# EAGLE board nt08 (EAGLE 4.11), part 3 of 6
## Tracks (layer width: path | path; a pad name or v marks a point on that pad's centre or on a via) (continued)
GND  (via drill 0.61) (continued)
  Bottom 0.254: IC7.12 -2.54,546.1 -6.35,542.29 -6.35,537.85 0.64,537.85 1.27,538.48 1.27,541.65 5.71,541.65 6.99,540.38 IC7.7 | M916_4.C2 44.45,574.04 44.45,578.49 8.26,578.49 IC8.7 | M916_2.T1 85.72,424.81 84.45,426.08 52.07,426.08 47.62,421.64 45.72,421.64 M916_2.C2 | IC47.7 247.01,90.81 245.75,89.53 v243.84,89.53 239.4,89.53 238.12,90.81 IC47.3 236.85,90.81 235.59,89.53 202.56,89.53 | 202.56,89.53 169.54,89.53 168.28,90.81 IC23.7 | 202.56,89.53 203.84,90.81 IC36.4 | v275.59,14.61 248.28,14.61 IC46.7 | IC46.6 244.47,14.61 243.21,13.34 239.4,13.34 238.12,14.61 IC46.3 236.85,15.88 235.59,17.14 206.38,17.14 205.1,15.88 IC34.4 203.84,14.61 202.56,13.34 169.54,13.34 168.28,14.61 IC22.7 167,15.88 165.74,17.14 89.53,17.14 88.27,15.88 IC16.7 87,14.61 85.72,13.34 46.35,13.34 | M916_21.C2 -35.56,313.06 -34.29,311.79 -24.13,311.79 -20.95,308.61 5.71,308.61 6.35,309.25 6.35,316.23 5.71,316.23 M916_21.T1 | 3.17,467.36 4.45,468.63 M916_23.T1 | 3.17,467.36 -34.29,467.36 -35.56,466.09 M916_23.C2 | 4.45,414.65 3.17,415.93 IC4.5 | 4.45,414.65 5.71,414.65 6.99,415.93 IC4.7 | 4.45,414.65 -15.88,394.33 -35.56,394.33 -35.56,389.89 M916_22.C2 | SV2.S -10.79,55.88 -12.06,55.88 SV2.P | SV7.A -27.3,71.12 -26.04,71.12 SV7.C | SV7.H -20.95,71.12 -22.23,71.12 SV7.E | SV7.S -10.79,71.12 -12.06,71.12 SV7.P | SV7.MM 13.34,71.12 14.61,71.12 SV7.PP 15.88,71.12 17.14,71.12 SV7.SS | SV6.A -27.3,38.1 -26.04,38.1 SV6.C -24.77,38.1 -23.5,38.1 SV6.E | SV6.AA -0.64,38.1 -1.91,38.1 SV6.Y | SV6.KK 10.79,38.1 12.06,38.1 SV6.MM 13.34,38.1 14.61,38.1 SV6.PP 15.88,38.1 17.14,38.1 SV6.SS 18.41,38.1 19.68,38.1 SV6.UU
  Bottom 0.254: 46.35,13.34 47.62,14.61 IC9.7 | 46.35,13.34 30.48,13.34 20.95,22.86 SV1.VV | SV4.S -10.79,137.16 -12.06,137.16 SV4.P | SV4.HH 6.99,137.16 5.71,137.16 SV4.EE | SV4.UU 19.68,137.16 18.41,137.16 SV4.SS | SV9.K -18.41,152.4 -19.68,152.4 SV9.H | SV9.P -12.06,152.4 -10.79,152.4 SV9.S -9.53,152.4 -8.26,152.4 SV9.U | SV9.Y -3.17,152.4 -4.45,152.4 SV9.W | SV9.CC 1.91,152.4 0.64,152.4 SV9.AA | SV9.EE 5.71,152.4 6.99,152.4 SV9.HH 8.26,152.4 9.53,152.4 SV9.KK | SV9.PP 14.61,152.4 13.34,152.4 SV9.MM | SV3.P -13.34,99.06 -14.61,99.06 SV3.M | SV3.PP 14.61,99.06 13.34,99.06 SV3.MM | SV3.UU 19.68,99.06 18.41,99.06 SV3.SS | SV8.A -27.3,119.38 -26.04,119.38 SV8.C | SV8.H -19.68,119.38 -18.41,119.38 SV8.K -17.14,119.38 -15.88,119.38 SV8.M | SV8.MM 13.34,119.38 14.61,119.38 SV8.PP 15.88,119.38 17.14,119.38 SV8.SS 18.41,119.38 19.68,119.38 SV8.UU | M916_19.C2 -35.56,224.79 -34.29,226.06 3.17,226.06 4.45,227.33 M916_19.T1 | SV10.A -27.3,190.5 -26.04,190.5 SV10.C | SV10.K -18.41,190.5 -19.68,190.5 SV10.H | SV10.Y -3.17,190.5 -4.45,190.5 SV10.W | SV5.U -6.99,173.99 -5.71,173.99 SV5.W -4.45,173.99 -3.17,173.99 SV5.Y | v13.34,255.91 -3.17,255.91 -11.43,264.16 IC1.23 | SV10.UU 19.68,190.5 18.41,190.5 SV10.SS | v45.72,250.19 14.61,250.19 IC1.12 | 3.17,467.36 12.06,467.36 14.61,469.9 38.1,469.9 38.1,473.71 38.73,474.35 47.62,474.35 48.9,473.07 IC15.7 | IC20.7 88.27,319.4 89.53,318.13 161.93,318.13 163.19,319.4 IC28.4 | v160.02,372.11 111.76,372.11 110.49,370.84 M916_9.M1 | M916_6.C2 85.09,135.89 86.36,137.16 107.95,137.16 109.22,135.89 M916_6.M2 | M916_7.V1 131.44,214.63 126.36,214.63 M916_7.T1 125.09,215.26 121.28,215.26
  Bottom 0.254: M916_7.J1 100.97,215.26 102.23,216.53 114.3,216.53 115.57,217.81 M916_7.P1 116.84,217.81 118.75,217.81 119.38,217.17 | 121.28,215.26 119.38,217.17 | 119.38,217.17 121.92,219.71 123.19,219.71 123.83,219.07 127.64,219.07 128.27,218.44 M916_7.U1 | 92.08,210.19 93.34,208.91 M916_7.F2 | 92.08,210.19 86.36,210.19 85.09,211.46 M916_7.C2 | 107.95,210.19 109.22,211.46 M916_7.M2 | 107.95,210.19 92.08,210.19 | M916_1.C2 83.82,224.16 83.82,218.44 M916_7.C1 | 121.28,215.26 121.28,210.19 107.95,210.19 | M916_7.T2 126.36,208.91 127,209.55 130.81,209.55 131.44,210.19 133.35,210.19 134.62,208.91 160.66,208.91 163.19,206.38 IC25.4 164.47,206.38 165.74,207.65 206.38,207.65 207.65,206.38 IC38.7 208.91,205.1 v242.57,205.1 | IC43.4 203.84,473.07 202.56,474.35 169.54,474.35 168.28,473.07 IC31.7 | 240.66,508.63 239.4,508.63 238.12,509.9 IC55.3 236.85,511.18 235.59,512.45 206.38,512.45 205.1,511.18 IC44.4 | 240.66,508.63 241.94,509.9 IC55.5 | 240.66,508.63 245.75,508.63 247.01,509.9 IC55.7 | IC45.6 205.1,548 203.84,546.74 200.03,546.74 198.75,548 IC45.3 197.49,548 196.22,546.74 165.74,546.74 | 165.74,546.74 130.18,546.74 128.91,548 IC21.7 | 165.74,546.74 167,548 IC32.7 | 249.56,394.33 248.28,395.61 IC54.7 | 249.56,394.33 286.38,394.33 287.65,395.61 IC66.7 | 249.56,394.33 241.3,394.33 241.3,397.51 240.66,398.14 206.38,398.14 205.1,396.88 IC41.4 | 245.75,280.04 231.78,280.04 231.14,280.67 209.55,280.67 208.91,281.31 IC39.7 | 245.75,280.04 247.01,281.31 IC53.7 | 245.75,280.04 286.38,280.04 287.65,281.31 IC63.7 | v247.65,266.7 244.47,263.52 IC52.4 | IC57.11 240.66,575.95 241.94,577.22 279.4,577.22 282.57,574.04 284.48,574.04 M916_13.C2
  Bottom 0.254: IC106.7 488.31,111.12 490.22,113.03 523.24,113.03 524.51,111.76 524.51,108.58 526.41,108.58 527.68,109.86 IC114.7 | 488.95,18.41 514.35,18.41 515.62,17.14 526.41,17.14 527.68,15.88 IC112.7 528.96,14.61 530.23,13.34 563.88,13.34 | 488.95,18.41 451.49,18.41 448.94,15.88 IC92.7 | 563.88,13.34 565.78,13.34 567.05,14.61 IC123.7 | 488.95,18.41 v488.95,17.78 | 563.88,13.34 563.88,16.51 583.57,36.2 595,36.2 600.08,41.27 IC126.11 | IC109.7 488.31,319.4 489.58,318.13 526.41,318.13 527.68,319.4 IC118.7 | IC121.7 528.96,452.75 542.92,438.79 546.74,438.79 548,437.51 IC124.23 549.27,437.51 563.25,451.49 597.53,451.49 | IC132.1 593.73,262.25 595,260.99 596.26,260.99 597.53,262.25 IC132.3 598.8,262.25 600.08,260.99 606.42,260.99 607.7,262.25 IC132.7 | IC125.7 568.33,521.34 574.04,527.05 605.79,527.05 607.7,528.96 IC140.7 | IC124.12 574.67,421 596.26,421 597.53,422.27 IC137.12 598.17,424.18 598.17,451.49 | 597.53,451.49 596.26,452.75 IC138.2 | 598.17,451.49 606.42,451.49 607.7,452.75 IC138.7 | 597.53,451.49 598.17,451.49 | v447.04,142.24 443.23,146.05 410.21,146.05 408.31,147.96 IC85.7 | IC86.7 407.04,224.16 403.86,220.98 378.46,220.98 372.75,215.26 M916_16.V1 371.48,215.26 368.94,217.81 M916_16.U1 368.3,217.81 365.76,215.26 M916_16.T1 365.12,214.63 363.86,213.36 326.39,213.36 325.12,212.09 M916_16.C2 | v369.57,502.92 368.94,502.29 328.3,502.29 327.02,501.01 M916_12.T1 | IC80.7 368.94,376.56 370.84,374.65 405.13,374.65 407.04,376.56 IC88.7 | v406.4,452.75 368.94,452.75 IC81.7 | v449.58,511.81 450.21,512.45 485.77,512.45 487.05,511.18 IC111.7 | IC99.7 447.68,433.7 446.4,432.44 434.98,432.44 433.7,433.7 IC99.1 432.44,433.7 v408.31,433.7
  Bottom 0.254: v440.69,302.26 368.94,302.26 IC79.7 | IC110.7 487.68,375.92 492.12,371.48 492.12,369.57 448.31,369.57 IC97.7 | IC87.7 408.31,243.21 415.29,236.22 440.69,236.22 447.04,242.57 447.04,245.11 441.32,250.82 IC94.11 | v323.85,319.4 288.93,319.4 IC64.7 | v83.82,109.86 48.9,109.86 IC11.7
I/O_0_TO_AC\  (via drill 0.61)
  Top 0.254: v161.29,150.5 156.84,146.05 v156.84,133.99 | v6.35,128.27 2.54,124.46 2.54,122.56 SV8.DD
  Bottom 0.254: v161.29,150.5 238.12,150.5 243.21,155.57 IC49.5 | v156.84,133.99 150.5,127.64 6.99,127.64 v6.35,128.27 | SV3.DD 2.54,102.23 2.54,118.11 3.17,118.11 3.81,118.75 3.81,121.28 2.54,121.28 SV8.DD
I/O_0_TO_AC\_  (via drill 0.61)
  Top 0.254: v242.57,553.09 241.94,552.45 241.94,539.12 241.3,538.48 241.3,535.94 243.21,534.03 243.21,531.5 243.84,530.86 243.84,514.35 243.21,513.72 243.21,512.45 243.84,511.81 243.84,387.35 248.92,382.27 248.92,293.37 250.82,291.46 v250.82,161.29 | v242.57,159.38 241.3,158.12 241.3,157.48 IC49.6
  Bottom 0.254: IC49.7 239.4,155.57 240.66,155.57 IC49.6 | v242.57,553.09 198.75,553.09 196.22,555.62 IC45.13 | v250.82,161.29 248.92,159.38 v242.57,159.38
I/O_1_TO_CA_INH\  (via drill 0.61)
  Top 0.254: v0,267.33 0,254 -2.54,251.46 -2.54,210.19 -1.91,209.55 -1.91,193.04 SV10.Z | v-2.54,188.59 -2.54,177.16 SV5.Z
  Bottom 0.254: v0,267.33 45.09,267.33 52.7,259.71 89.53,259.71 94.61,264.8 120.02,264.8 121.28,263.52 227.33,263.52 228.6,264.8 239.4,264.8 240.66,263.52 IC52.3 | v-2.54,188.59 -1.27,189.87 -1.27,192.41 -2.54,192.41 SV10.Z
I/O_1_TO_CA_INH\_  (via drill 0.61)
  Top 0.254: v232.41,260.35 232.41,131.44 234.31,129.54 234.31,118.11 233.68,117.47 233.68,93.98 232.41,92.71 IC47.1
  Bottom 0.254: v232.41,260.35 234.31,262.25 235.59,262.25 IC52.1 236.85,262.25 238.12,262.25 IC52.2
I/O_ADDR_ACC\  (via drill 0.61)
  Top 0.254: v351.15,464.19 351.15,539.12 353.69,539.12 354.96,537.85 IC82.13 | v250.82,459.74 246.38,455.3 v246.38,407.67 | v64.77,408.31 64.77,254 64.14,253.37 64.14,157.48 v64.77,156.84 | SV9.JJ 7.62,154.31 8.89,153.03 8.89,141.6 7.62,140.34 SV4.JJ
  Bottom 0.254: v351.15,464.19 346.71,459.74 v250.82,459.74 | v246.38,407.67 245.75,408.31 v64.77,408.31 | v64.77,156.84 59.05,151.13 45.72,151.13 33.02,138.43 9.53,138.43 8.26,139.7 SV4.JJ
I/O_B-BRK  (via drill 0.61)
  Top 0.254: v365.12,244.47 365.12,245.75 363.86,247.01 363.86,300.36 363.22,300.99 IC79.5 | v222.88,231.14 222.25,230.5 v222.25,164.47 | SV4.DD 2.54,140.34 1.27,141.6 1.27,153.03 2.54,154.31 SV9.DD
  Bottom 0.254: v365.12,244.47 355.6,234.95 318.77,234.95 316.23,237.49 229.24,237.49 v222.88,231.14 | v222.25,164.47 216.53,158.75 64.14,158.75 60.96,155.57 21.59,155.57 20.95,156.21 4.45,156.21 3.17,154.94 SV9.DD
I/O_B-RUN  (via drill 0.61)
  Top 0.254: v355.6,224.79 355.6,277.5 354.96,278.13 354.96,300.36 355.6,300.99 IC79.2 | v189.87,142.88 v189.87,220.98 | v8.26,128.91 7.62,128.27 7.62,122.56 SV8.JJ
  Bottom 0.254: v355.6,224.79 353.06,222.25 278.76,222.25 276.86,220.34 190.5,220.34 v189.87,220.98 | v189.87,142.88 184.15,137.16 128.27,137.16 120.02,128.91 v8.26,128.91 | SV3.JJ 7.62,102.23 7.62,118.11 8.26,118.11 8.89,118.75 8.89,121.28 7.62,121.28 SV8.JJ
I/O_BAC_00  (via drill 0.61)
  Top 0.254: v377.82,13.34 394.33,-3.17 IC83.2 | v250.19,13.34 243.21,6.35 v49.53,6.35 | SV6.D -25.4,40.01 -26.67,38.73 -26.67,24.77 -25.4,23.5 SV1.D
  Bottom 0.254: v250.19,13.34 v377.82,13.34 | v49.53,6.35 47.62,8.26 -12.7,8.26 -24.13,19.68 -24.13,22.23 -25.4,22.23 SV1.D
I/O_BAC_01  (via drill 0.61)
  Top 0.254: v401.32,21.59 401.32,-1.27 402.59,-2.54 IC83.5 | v-19.05,26.04 -19.05,24.77 -20.32,23.5 SV1.J
  Bottom 0.254: v401.32,21.59 400.69,20.95 288.93,20.95 285.75,24.13 248.92,24.13 247.01,26.04 v-19.05,26.04 -21.59,28.57 -21.59,40.64 -20.95,40.64 SV6.J
I/O_BAC_02  (via drill 0.61)
  Top 0.254: v387.99,154.31 380.37,146.69 378.46,146.69 v378.46,147.32 | v123.83,133.99 v123.83,27.94 | v-10.16,28.57 -15.24,23.5 SV1.N
  Bottom 0.254: v387.99,154.31 400.69,154.31 401.95,155.57 IC85.10 | v378.46,147.32 375.92,144.78 248.28,144.78 247.65,144.15 133.99,144.15 v123.83,133.99 | v123.83,27.94 123.19,27.3 -8.89,27.3 v-10.16,28.57 -13.97,32.38 -13.97,40.01 -15.24,40.01 SV6.N
I/O_BAC_03  (via drill 0.61)
  Top 0.254: v401.32,91.44 401.32,82.55 402.59,81.28 IC84.10 | v184.78,97.16 179.07,91.44 v179.07,41.27 | v-8.89,28.57 -8.89,24.77 -10.16,23.5 SV1.T
  Bottom 0.254: v401.32,91.44 396.24,96.52 226.69,96.52 226.06,97.16 v184.78,97.16 | v179.07,41.27 167,29.21 -3.17,29.21 -5.71,31.75 | -5.71,31.75 -11.43,37.47 -11.43,40.64 -10.79,40.64 SV6.T | v-8.89,28.57 -5.71,31.75
I/O_BAC_04  (via drill 0.61)
  Top 0.254: v31.75,34.92 v31.75,78.11 | v-2.54,34.92 -2.54,26.04 -5.08,23.5 SV1.X
  Bottom 0.254: v31.75,78.11 316.23,78.11 316.23,81.28 318.13,83.19 391.8,83.19 394.33,80.64 IC84.13 | v31.75,34.92 -1.27,34.92 -1.91,35.56 | -1.91,35.56 -3.81,37.47 -3.81,40.01 -5.08,40.01 SV6.X | v-2.54,34.92 -1.91,35.56
I/O_BAC_05  (via drill 0.61)
  Top 0.254: v69.22,130.18 63.5,124.46 v63.5,56.52 | v0,36.2 0,23.5 SV1.BB
  Bottom 0.254: v69.22,130.18 106.68,130.18 121.28,144.78 247.01,144.78 247.65,145.41 334.64,145.41 338.45,149.22 380.37,149.22 382.9,146.69 393.06,146.69 394.33,147.96 IC85.2 | v63.5,56.52 55.24,48.26 -3.17,48.26 -4.45,46.99 -4.45,41.91 -1.91,41.91 -0.64,40.64 SV6.BB 0,40.01 1.27,40.01 1.27,37.47 v0,36.2
I/O_BAC_06  (via drill 0.61)
  Top 0.254: v402.59,128.91 402.59,147.32 IC85.5 | v119.38,106.05 114.3,100.97 114.3,55.24 v95.25,36.2 | v7.62,36.2 7.62,26.04 5.08,23.5 SV1.FF
  Bottom 0.254: v402.59,128.91 399.42,125.73 292.1,125.73 291.46,126.36 262.25,126.36 244.47,108.58 219.07,108.58 218.44,109.22 179.07,109.22 175.26,105.41 120.02,105.41 v119.38,106.05 | v95.25,36.2 v7.62,36.2 6.35,37.47 6.35,40.01 5.08,40.01 SV6.FF
I/O_BAC_07  (via drill 0.61)
  Top 0.254: v398.78,48.26 398.78,67.31 402.59,71.12 IC84.5 | v95.89,49.53 v87.63,41.27 | SV1.LL 10.79,22.86 12.06,21.59 16.51,21.59 16.51,41.27 15.88,41.91 10.16,41.91 10.16,41.27 SV6.LL
  Bottom 0.254: v398.78,48.26 398.14,47.62 276.23,47.62 273.05,50.8 210.82,50.8 209.55,49.53 v95.89,49.53 | v87.63,41.27 85.72,39.37 12.06,39.37 10.79,40.64 SV6.LL
I/O_BAC_08  (via drill 0.61)
  Top 0.254: v232.41,10.79 207.01,10.79 205.1,8.89 51.44,8.89 v51.44,14.61 | SV6.RR 15.24,40.01 13.97,38.73 13.97,24.77 15.24,23.5 SV1.RR
  Bottom 0.254: v232.41,10.79 395.61,10.79 401.95,4.45 IC83.10 | v51.44,14.61 45.72,20.32 24.77,20.32 20.95,24.13 17.14,24.13 15.88,22.86 SV1.RR
I/O_BAC_09  (via drill 0.61)
  Top 0.254: v262.89,4.45 -11.43,4.45 v-11.43,9.53 | v-25.4,26.04 -22.86,23.5 SV1.F
  Bottom 0.254: v262.89,4.45 267.97,-0.64 390.52,-0.64 394.33,3.17 IC83.13 | v-11.43,9.53 -21.59,19.68 -21.59,22.23 -22.86,22.23 SV1.F | v-25.4,26.04 -29.21,26.04 -29.21,38.73 -28.57,39.37 -24.77,39.37 -23.5,40.64 SV6.F
I/O_BAC_10  (via drill 0.61)
  Top 0.254: v396.24,13.97 396.24,69.85 394.97,71.12 IC84.2 | v231.14,7.62 v235.59,12.06 | v-19.05,27.3 -17.78,26.04 -17.78,23.5 SV1.L
  Bottom 0.254: v396.24,13.97 394.33,12.06 v235.59,12.06 | v231.14,7.62 229.87,8.89 -5.71,8.89 -16.51,19.68 -16.51,22.23 -17.78,22.23 SV1.L | v-19.05,27.3 -19.05,38.73 -17.78,40.01 SV6.L
I/O_BAC_11  (via drill 0.61)
  Top 0.254: v401.32,114.3 401.32,149.86 398.78,152.4 398.78,158.12 396.88,158.12 395.61,156.84 IC85.13 | v213.36,98.42 208.91,93.98 208.91,13.97 v205.1,10.16
  Bottom 0.254: v401.32,114.3 391.8,104.78 219.71,104.78 v213.36,98.42 | v205.1,10.16 204.47,10.79 31.75,10.79 20.95,21.59 -10.79,21.59 -12.06,22.86 SV1.R -13.34,22.86 -15.24,24.77 -31.75,24.77 -31.75,38.73 -28.57,41.91 -14.61,41.91 -13.34,40.64 SV6.R
I/O_BMB_00  (via drill 0.61)
  Top 0.254: v340.36,306.7 338.45,304.8 338.45,200.03 335.92,197.49 335.92,185.42 336.55,184.78 336.55,149.86 v337.19,149.22 | v109.22,137.16 98.42,126.36 v98.42,86.36 | SV2.D -25.4,59.05 -26.67,60.33 -26.67,71.75 -25.4,73.03 SV7.D
  Bottom 0.254: v340.36,306.7 352.43,306.7 354.96,309.25 IC79.13 | v337.19,149.22 334.01,146.05 247.01,146.05 246.38,145.41 117.47,145.41 v109.22,137.16 | v98.42,86.36 97.79,85.72 -12.7,85.72 -24.77,73.66 SV7.D
I/O_BMB_01  (via drill 0.61)
  Top 0.254: v354.33,277.5 354.33,374.65 355.6,375.92 IC80.2 | v231.14,276.23 v231.14,185.42 | v52.7,185.42 50.16,182.88 v50.16,75.56 | v-20.32,69.22 -20.32,59.05 SV2.J
  Bottom 0.254: v354.33,277.5 353.69,278.13 241.94,278.13 240.03,276.23 v231.14,276.23 | v231.14,185.42 v52.7,185.42 | v50.16,75.56 49.53,74.93 -18.41,74.93 -19.68,73.66 SV7.J -20.32,73.03 -19.05,73.03 -19.05,70.48 v-20.32,69.22
I/O_BMB_02  (via drill 0.61)
  Top 0.254: v361.95,478.15 361.95,527.05 363.22,528.32 IC82.5 | v151.13,476.25 150.5,475.62 150.5,363.86 151.76,362.58 v151.76,102.23 | v23.5,101.6 v23.5,55.88 | v-13.97,64.14 -15.24,62.87 -15.24,59.05 SV2.N
  Bottom 0.254: v361.95,478.15 358.14,474.35 277.5,474.35 276.23,475.62 151.76,475.62 v151.13,476.25 | v151.76,102.23 137.16,102.23 135.25,104.14 26.04,104.14 v23.5,101.6 | v23.5,55.88 22.23,57.15 -13.34,57.15 -14.61,58.42 SV2.N | v-13.97,64.14 -13.97,71.75 -15.24,73.03 SV7.N
I/O_BMB_03  (via drill 0.61)
  Top 0.254: v-5.08,69.22 -5.08,59.05 SV2.X | IC86.1 392.43,226.06 391.16,227.33 391.16,393.7 392.43,394.97 IC89.1 | v365.76,396.88 365.76,449.58 363.22,452.12 IC81.5 | v8.89,87 -4.45,73.66 SV7.X | v133.35,88.9 133.99,89.53 133.99,201.29 135.89,203.2 135.89,219.07 v134.62,220.34
  Bottom 0.254: v-5.08,69.22 -3.81,70.48 -3.81,73.03 -5.08,73.03 SV7.X | v365.76,396.88 391.8,396.88 IC89.1 | v8.89,87 9.53,86.36 97.16,86.36 99.69,88.9 v133.35,88.9 | v134.62,220.34 135.25,219.71 288.93,219.71 290.83,221.62 389.25,221.62 391.8,224.16 IC86.1
I/O_BMB_03\  (via drill 0.61)
  Top 0.254: v-10.16,69.22 -10.16,59.05 SV2.T
  Bottom 0.254: v-10.16,69.22 -8.89,70.48 -8.89,73.03 -10.16,73.03 SV7.T
I/O_BMB_04  (via drill 0.61)
  Top 0.254: v5.08,69.22 5.08,59.05 SV2.FF | IC89.2 394.97,394.97 394.97,387.99 393.7,386.71 393.7,231.14 394.33,230.5 394.33,226.69 394.97,226.06 IC86.2 394.97,223.52 394.97,202.56 v393.7,201.29 | v367.03,395.61 367.03,455.93 363.22,459.74 IC81.10 | v11.43,79.38 5.71,73.66 SV7.FF | v219.71,83.82 220.98,85.09 v220.98,201.93
  Bottom 0.254: v5.08,69.22 6.35,70.48 6.35,73.03 5.08,73.03 SV7.FF | v367.03,395.61 368.3,394.33 393.06,394.33 394.33,395.61 IC89.2 | v11.43,79.38 13.34,81.28 16.51,81.28 19.05,83.82 v219.71,83.82 | v220.98,201.93 317.5,201.93 318.77,203.2 381.63,203.2 383.54,201.29 v393.7,201.29
I/O_BMB_04\  (via drill 0.61)
  Top 0.254: v0,69.22 0,59.05 SV2.BB
  Bottom 0.254: v0,69.22 1.27,70.48 1.27,73.03 0,73.03 SV7.BB
I/O_BMB_05  (via drill 0.61)
  Top 0.254: SV2.RR 15.24,59.05 13.97,60.33 13.97,71.75 15.24,73.03 SV7.RR 15.24,74.3 v15.24,83.19 | 396.24,393.7 396.24,227.33 397.51,226.06 IC86.3 397.51,223.52 397.51,167 v393.7,163.19 | 396.24,393.7 397.51,394.97 IC89.3 | v395.61,464.19 396.24,463.55 396.24,393.7 | v308.61,160.66 v308.61,87
  Bottom 0.254: v395.61,464.19 362.58,464.19 361.31,462.92 357.5,462.92 356.24,461.64 IC81.13 | v15.24,83.19 17.14,85.09 163.83,85.09 164.47,85.72 307.34,85.72 v308.61,87 | v308.61,160.66 311.15,163.19 v393.7,163.19
I/O_BMB_05\  (via drill 0.61)
  Top 0.254: v10.16,69.22 10.16,59.05 SV2.LL
  Bottom 0.254: v10.16,69.22 11.43,70.48 11.43,73.03 10.16,73.03 SV7.LL
I/O_BMB_06  (via drill 0.61)
  Top 0.254: v-17.78,69.22 -17.78,59.05 SV2.L | IC86.4 400.05,226.06 398.78,227.33 398.78,392.43 400.05,393.7 400.05,394.97 IC89.4 | v354.33,400.69 354.33,527.05 355.6,528.32 IC82.2 | v57.15,90.81 58.42,92.08 v58.42,133.99 | v368.3,155.57 367.67,156.21 367.67,221.62 v368.94,222.88
  Bottom 0.254: SV7.L -17.78,73.03 -16.51,73.03 -16.51,70.48 v-17.78,69.22 -19.05,67.94 -26.67,67.94 -29.21,70.48 -29.21,90.81 v57.15,90.81 | v354.33,400.69 356.87,398.14 398.14,398.14 399.42,396.88 IC89.4 | v58.42,133.99 70.48,146.05 245.75,146.05 255.27,155.57 v368.3,155.57 | v368.94,222.88 370.84,224.79 389.89,224.79 391.8,226.69 398.14,226.69 399.42,225.43 IC86.4
I/O_BMB_06\
  Top 0.254: SV2.F -23.5,58.42 -24.77,57.15 -26.67,57.15 -26.67,59.05 -29.21,61.59 -29.21,74.3 -28.57,74.93 -22.86,74.93 -22.86,74.3 SV7.F
I/O_BMB_07  (via drill 0.61)
  Top 0.254: v-7.62,69.22 -7.62,59.05 SV2.V | IC89.5 402.59,394.97 401.32,393.7 401.32,227.33 402.59,226.06 IC86.5 402.59,223.52 403.86,222.25 v403.86,81.92 | v355.6,400.69 355.6,452.12 IC81.2 | v-4.45,76.2 -6.99,73.66 SV7.V
  Bottom 0.254: v-7.62,69.22 -6.35,70.48 -6.35,73.03 -7.62,73.03 SV7.V | v355.6,400.69 357.5,398.78 400.05,398.78 401.95,396.88 IC89.5 | v-4.45,76.2 49.53,76.2 50.8,77.47 402.59,77.47 403.86,78.74 v403.86,81.92
I/O_BMB_07\
  Top 0.254: SV2.R -13.34,58.42 -14.61,57.15 -21.59,57.15 -21.59,71.75 -20.95,72.39 -13.34,72.39 -13.34,73.66 SV7.R
I/O_BMB_08  (via drill 0.61)
  Top 0.254: v2.54,69.22 2.54,59.05 SV2.DD | v361.31,390.52 361.95,389.89 361.95,379.73 363.22,378.46 IC80.5 363.22,375.92 363.22,318.13 364.49,316.87 364.49,273.69 v365.12,273.05 | v335.92,55.88 335.92,184.15 335.28,184.78 335.28,205.74 335.92,206.38 v335.92,262.25
  Bottom 0.254: 3.17,69.85 3.81,70.48 3.81,73.03 2.54,73.03 SV7.DD | 3.17,69.85 v2.54,69.22 | v361.31,390.52 364.49,393.7 402.59,393.7 404.5,395.61 IC89.6 | 3.17,69.85 9.53,63.5 66.67,63.5 75.56,54.61 115.57,54.61 118.75,57.78 323.85,57.78 327.02,54.61 334.64,54.61 v335.92,55.88 | v335.92,262.25 346.71,273.05 v365.12,273.05
I/O_BMB_08\  (via drill 0.61)
  Top 0.254: v405.13,163.83 405.13,223.52 IC86.6 | v284.48,158.75 284.48,96.52 280.67,92.71 v280.67,83.82 | v1.91,77.47 -1.91,73.66 SV7.Z | v-2.54,69.22 -2.54,59.05 SV2.Z
  Bottom 0.254: v405.13,163.83 400.05,158.75 v284.48,158.75 | v280.67,83.82 279.4,82.55 97.79,82.55 97.16,83.19 19.68,83.19 13.97,77.47 v1.91,77.47 | v-2.54,69.22 -1.27,70.48 -1.27,73.03 -2.54,73.03 SV7.Z
I/O_BMB_09  (via drill 0.61)
  Top 0.254: v364.49,318.13 364.49,382.27 363.22,383.54 IC80.10 | v147.32,312.42 142.24,307.34 v142.24,256.54 | v55.88,255.91 53.98,254 53.98,182.88 52.07,180.97 52.07,75.56 52.7,74.93 52.7,74.3 50.8,72.39 v50.8,69.85 | v8.89,65.41 8.89,60.33 7.62,59.05 SV2.JJ
  Bottom 0.254: v364.49,318.13 362.58,316.23 151.13,316.23 v147.32,312.42 | v142.24,256.54 141.6,255.91 v55.88,255.91 | v50.8,69.85 47.62,66.67 11.43,66.67 10.79,67.31 | 10.79,67.31 8.89,69.22 8.89,73.03 7.62,73.03 SV7.JJ | 10.79,67.31 v8.89,65.41
I/O_BMB_10  (via drill 0.61)
  Top 0.254: v352.43,331.47 352.43,374.01 354.33,375.92 354.33,382.27 355.6,383.54 IC80.13 | v301.62,327.66 300.99,327.02 300.99,285.75 300.36,285.12 300.36,258.44 297.18,255.27 297.18,179.71 296.55,179.07 v296.55,84.45 | SV7.NN 12.7,74.3 v12.7,81.92 12.7,84.45 15.24,84.45 16.51,83.19 16.51,57.15 14.61,57.15 13.34,58.42 SV2.NN
  Bottom 0.254: v352.43,331.47 348.62,327.66 v301.62,327.66 | v296.55,84.45 295.91,85.09 165.1,85.09 164.47,84.45 17.78,84.45 15.24,81.92 v12.7,81.92
I/O_BMB_11  (via drill 0.61)
  Top 0.254: v359.41,464.19 359.41,532.13 363.22,535.94 IC82.10 | v189.23,458.47 187.32,456.56 187.32,384.81 188.59,383.54 188.59,288.93 187.32,287.65 187.32,243.21 v187.96,242.57 | v55.88,240.66 54.61,239.4 54.61,182.25 52.7,180.34 52.7,76.2 53.34,75.56 v53.34,73.66 | v19.05,67.94 19.05,60.33 17.78,59.05 SV2.TT
  Bottom 0.254: v359.41,464.19 358.77,463.55 351.79,463.55 346.71,458.47 v189.23,458.47 | v187.96,242.57 185.42,240.03 81.28,240.03 80.64,240.66 v55.88,240.66 | v53.34,73.66 52.07,72.39 23.5,72.39 | 23.5,72.39 19.68,72.39 18.41,73.66 SV7.TT | 23.5,72.39 v19.05,67.94
I/O_BRK_RQ\  (via drill 0.61)
  Top 0.254: v245.11,158.12 245.11,115.57 241.3,111.76 IC48.3 | SV4.V -7.62,140.34 -8.89,141.6 -8.89,153.03 -7.62,154.31 SV9.V
  Bottom 0.254: v245.11,158.12 64.77,158.12 61.59,154.94 22.23,154.94 20.95,153.67 -5.71,153.67 -6.99,154.94 SV9.V
I/O_BRK_RQ\_  (via drill 0.61)
  Top 0.254: IC48.1 236.85,109.86 238.12,109.86 IC48.2 | v186.69,114.3 186.69,171.45 181.61,176.53 181.61,193.04 184.15,195.58 184.15,303.53 183.51,304.17 183.51,311.15 186.06,313.69 186.06,368.94 185.42,369.57 185.42,539.75 193.04,547.37 IC45.1
  Bottom 0.254: v186.69,114.3 189.87,111.12 235.59,111.12 IC48.1
I/O_BWC0\  (via drill 0.61)
  Top 0.254: v362.58,313.06 362.58,311.79 363.22,311.15 IC79.10 | v76.2,309.88 70.48,304.17 70.48,217.17 v73.66,214 | v8.89,212.09 2.54,205.74 2.54,193.68 SV10.DD | v2.54,188.59 2.54,177.16 SV5.DD
  Bottom 0.254: v362.58,313.06 361.95,313.69 332.11,313.69 331.47,314.32 151.76,314.32 147.32,309.88 v76.2,309.88 | v73.66,214 71.75,212.09 v8.89,212.09 | v2.54,188.59 3.81,189.87 3.81,192.41 2.54,192.41 SV10.DD
I/O_DATA_IN  (via drill 0.61)
  Top 0.254: v245.75,187.96 245.11,188.59 245.11,229.87 243.84,231.14 IC51.5 | v69.85,186.69 65.41,182.25 v65.41,164.47 | SV4.Z -2.54,140.34 -3.81,141.6 -3.81,153.03 -2.54,154.31 SV9.Z
  Bottom 0.254: v245.75,187.96 245.11,188.59 234.95,188.59 233.04,186.69 v69.85,186.69 | v65.41,164.47 57.78,156.84 0,156.84 -1.91,154.94 SV9.Z
I/O_DATA_IN_  (via drill 0.61)
  Top 0.254: v226.06,231.14 224.79,229.87 224.79,125.73 227.33,123.19 227.33,12.06 234.31,12.06 236.22,13.97 236.22,20.32 234.95,21.59 IC46.13
  Bottom 0.254: v226.06,231.14 226.69,230.5 236.85,230.5 238.12,231.78 IC51.7 239.4,231.78 240.66,231.78 IC51.6
I/O_INT_RQ\  (via drill 0.61)
  Top 0.254: v242.57,128.27 242.57,120.65 243.84,119.38 IC48.5 | v3.81,127.64 -1.91,121.92 SV8.Z
  Bottom 0.254: v242.57,128.27 239.4,131.44 155.57,131.44 151.13,127 4.45,127 v3.81,127.64 | SV3.Z -2.54,102.23 -2.54,118.11 -1.91,118.11 -1.27,118.75 -1.27,121.28 -2.54,121.28 SV8.Z
I/O_INT_RQ\_  (via drill 0.61)
  Top 0.254: v210.82,550.54 216.53,544.83 v216.53,272.42 | v232.41,269.88 234.31,267.97 234.31,130.81 234.95,130.18 234.95,116.84 235.59,116.2 238.12,116.2 238.12,117.47 IC48.7
  Bottom 0.254: IC48.7 239.4,117.47 240.66,117.47 IC48.6 | v210.82,550.54 202.56,550.54 201.29,549.27 IC45.4 | v216.53,272.42 219.07,269.88 v232.41,269.88
I/O_PWR_CLR  (via drill 0.61)
  Top 0.254: v227.97,464.19 228.6,463.55 228.6,295.27 227.33,294 227.33,267.33 229.87,264.8 229.87,168.91 231.78,167 v231.78,118.75 | v62.23,117.47 61.59,116.84 v61.59,41.27 | SV1.TT 17.78,23.5 19.05,24.77 19.05,38.73 17.78,40.01 SV6.TT
  Bottom 0.254: v227.97,464.19 228.6,463.55 328.93,463.55 335.28,469.9 397.51,469.9 399.42,471.81 IC90.4 | v231.78,118.75 231.14,119.38 188.59,119.38 187.96,120.02 76.83,120.02 74.3,117.47 v62.23,117.47 | v61.59,41.27 60.96,40.64 22.23,40.64 20.95,41.91 19.68,41.91 18.41,40.64 SV6.TT
I/O_SKP_RQ\  (via drill 0.61)
  Top 0.254: v241.3,128.27 241.3,147.32 IC49.3 | v-2.54,126.36 -6.99,121.92 SV8.V
  Bottom 0.254: v241.3,128.27 207.01,128.27 205.74,127 193.68,127 193.04,126.36 v-2.54,126.36 | SV3.V -7.62,102.23 -7.62,118.11 -6.99,118.11 -6.35,118.75 -6.35,121.28 -7.62,121.28 SV8.V
I/O_SKP_RQ\_  (via drill 0.61)
  Top 0.254: v219.07,383.54 219.07,558.16 205.1,558.16 203.84,556.89 IC45.10 | v247.65,380.37 248.28,379.73 248.28,291.46 250.19,289.56 250.19,161.93 248.92,160.66 v248.92,155.57
  Bottom 0.254: IC49.1 236.85,147.96 238.12,147.96 IC49.2 239.4,149.22 240.66,150.5 243.84,150.5 v248.92,155.57 | v219.07,383.54 222.25,380.37 v247.65,380.37
I/O_TS03  (via drill 0.61)
  Top 0.254: v392.43,256.54 392.43,375.92 IC88.1 | v291.46,248.28 292.1,247.65 292.1,191.77 289.56,189.23 v289.56,50.8 | v98.42,50.8 v87.63,40.01 | SV1.JJ 6.99,22.86 5.71,21.59 -1.27,21.59 -1.27,38.73 -0.64,39.37 6.99,39.37 6.99,40.64 SV6.JJ
  Bottom 0.254: v392.43,256.54 391.8,255.91 362.58,255.91 360.05,253.37 332.11,253.37 327.02,248.28 v291.46,248.28 | v289.56,50.8 288.93,51.44 210.19,51.44 209.55,50.8 v98.42,50.8 | v87.63,40.01 84.45,36.83 9.53,36.83 8.89,37.47 8.89,40.01 7.62,40.01 SV6.JJ
I/O_TS04
  Top 0.254: SV1.NN 12.7,23.5 11.43,24.77 11.43,38.73 12.7,40.01 SV6.NN
IM_00\  (via drill 0.61)
  Top 0.254: SV3.D -25.4,102.23 -26.67,103.5 -26.67,120.02 -25.4,121.28 SV8.D | IC33.3 161.29,588.01 161.29,588.64 164.47,588.64 170.81,582.29 170.81,471.81 168.91,469.9 168.91,464.19 170.18,462.92 170.18,417.19 171.45,415.93 171.45,363.22 v172.09,362.58 172.09,339.73 v171.45,339.09 | v71.75,144.78 71.12,145.41 71.12,214 66.67,218.44 v66.67,327.02
  Bottom 0.254: v172.09,362.58 197.49,362.58 201.29,358.77 IC40.3 | v71.75,144.78 70.48,144.78 55.88,130.18 -17.78,130.18 -25.4,122.56 SV8.D | v66.67,327.02 78.74,339.09 v171.45,339.09
IM_00\_  (via drill 0.61)
  Top 0.254: 159.38,560.71 158.75,561.34 158.75,585.47 IC33.2 | 159.38,560.71 162.56,557.53 IC32.10 | 156.21,391.16 157.48,389.89 157.48,372.11 162.56,367.03 v162.56,363.86 | 156.21,391.16 152.4,394.97 IC30.1 | 159.38,560.71 156.21,557.53 156.21,391.16
  Bottom 0.254: IC33.1 156.84,586.11 158.12,586.11 IC33.2 | IC40.2 198.75,357.5 197.49,357.5 IC40.1 196.22,358.77 167.64,358.77 v162.56,363.86
IM_01\  (via drill 0.61)
  Top 0.254: v183.51,368.94 173.99,378.46 173.99,582.93 163.83,593.09 IC33.5 | v-6.35,178.44 -6.35,169.54 -11.43,164.47 -11.43,131.44 -20.32,122.56 SV8.J | v146.05,184.15 149.22,187.32 149.22,224.79 151.13,226.69 151.13,361.95 v150.5,362.58
  Bottom 0.254: SV3.J -20.32,102.23 -20.32,118.11 -20.95,118.11 -21.59,118.75 -21.59,121.92 -20.95,121.92 SV8.J | IC40.5 203.84,366.39 201.29,368.94 v183.51,368.94 156.84,368.94 v150.5,362.58 | v-6.35,178.44 -5.08,179.71 52.7,179.71 57.15,184.15 v146.05,184.15
IM_01\_  (via drill 0.61)
  Top 0.254: 157.48,588.64 157.48,591.82 158.75,593.09 IC33.7 159.38,593.73 160.66,593.73 IC33.6 | 157.48,588.64 157.48,560.07 154.94,557.53 IC32.13 | v196.85,393.7 199.39,391.16 199.39,367.03 IC40.7 | 157.48,588.64 160.02,588.64 160.02,561.34 163.83,557.53 163.83,401.32 160.02,397.51 IC30.4
  Bottom 0.254: IC40.7 200.03,365.12 201.29,365.12 IC40.6 | v196.85,393.7 188.59,393.7 187.96,393.06 163.19,393.06 160.66,395.61 IC30.4
IM_02\  (via drill 0.61)
  Top 0.254: v-3.17,46.99 -11.43,55.24 -11.43,95.89 -13.97,98.42 -13.97,99.69 -15.24,100.97 SV3.N -15.24,102.23 -16.51,103.5 -16.51,120.02 -15.24,121.28 SV8.N | IC34.3 202.56,14.61 203.84,13.34 205.74,13.34 205.74,18.41 206.38,19.05 v206.38,43.81 207.65,45.09 207.65,177.8 209.55,179.71 209.55,290.83 207.65,292.74 207.65,393.06 v208.28,393.7
  Bottom 0.254: v206.38,43.81 204.47,45.72 74.3,45.72 73.03,46.99 v-3.17,46.99 | v208.28,393.7 204.47,393.7 202.56,395.61 IC41.3
IM_02\_  (via drill 0.61)
  Top 0.254: v194.31,394.97 194.94,394.33 194.94,367.67 195.58,367.03 195.58,293.37 194.31,292.1 194.31,208.28 193.04,207.01 IC38.1 | IC41.2 198.75,395.61 197.49,395.61 IC41.1 | v193.68,17.78 190.5,20.95 190.5,140.34 191.13,140.97 v191.13,202.56
  Bottom 0.254: IC34.2 198.75,14.61 197.49,14.61 IC34.1 196.22,15.88 194.31,17.78 v193.68,17.78 | IC41.1 196.22,395.61 194.94,395.61 v194.31,394.97 171.45,394.97 163.19,403.23 IC30.10 | v191.13,202.56 193.04,204.47 IC38.1
IM_03\  (via drill 0.61)
  Top 0.254: 203.2,24.13 202.56,24.77 198.12,24.77 198.12,13.34 195.58,10.79 69.22,10.79 v69.22,87.63 | 203.2,24.13 203.84,23.5 IC34.5 | 203.2,24.13 203.2,62.23 206.38,65.41 206.38,137.79 204.47,139.7 204.47,290.83 203.2,292.1 203.2,401.32 204.47,402.59 IC41.5
  Bottom 0.254: v69.22,87.63 64.77,92.08 -2.54,92.08 -8.89,98.42 -8.89,100.97 -10.16,100.97 SV3.T -10.16,102.23 -8.89,102.23 -8.89,120.02 -10.16,121.28 SV8.T
IM_03\_  (via drill 0.61)
  Top 0.254: 200.66,22.23 201.29,22.23 IC34.6 | 200.66,22.23 200.03,22.23 IC34.7 | v200.66,182.25 200.66,204.47 IC38.4 | v212.72,176.53 213.36,175.9 213.36,99.69 208.28,94.61 208.28,14.61 206.38,12.7 200.66,12.7 200.66,22.23 | v226.06,399.42 226.69,398.78 226.69,350.52 227.97,349.25 227.97,295.91 226.06,294 226.06,250.19 227.97,248.28 227.97,184.15 v226.06,182.25
  Bottom 0.254: IC30.13 155.57,404.5 156.84,405.76 168.28,405.76 172.09,401.95 197.49,401.95 198.75,403.23 IC41.7 200.03,403.23 201.29,403.23 IC41.6 202.56,403.23 206.38,399.42 v226.06,399.42 | v200.66,182.25 206.38,176.53 v212.72,176.53 220.34,176.53 v226.06,182.25
IM_04\  (via drill 0.61)
  Top 0.254: v198.12,69.22 198.12,58.42 201.93,54.61 IC35.3 | v109.86,72.39 96.52,85.72 v96.52,95.89 | v209.55,432.44 210.19,431.8 210.19,381.63 208.91,380.37 208.91,294 210.82,292.1 210.82,178.44 210.19,177.8 v210.19,130.18 | v193.04,72.39 v193.04,127.64
  Bottom 0.254: v198.12,69.22 194.94,72.39 v193.04,72.39 v109.86,72.39 | v96.52,95.89 95.89,96.52 -1.91,96.52 -3.81,98.42 -3.81,100.97 -5.08,100.97 SV3.X -5.08,102.23 -3.81,102.23 -3.81,120.02 -5.08,121.28 SV8.X | v209.55,432.44 203.84,432.44 202.56,433.7 IC42.3 | v210.19,130.18 208.91,128.91 206.38,128.91 205.1,127.64 v193.04,127.64
IM_04\_  (via drill 0.61)
  Top 0.254: IC42.1 197.49,433.7 198.75,433.7 IC42.2 | v154.94,434.34 154.94,468.63 152.4,471.17 IC31.1 | IC35.1 197.49,52.7 198.75,52.7 IC35.2 | v201.93,172.09 201.93,207.01 203.2,208.28 203.2,212.09 IC38.10 203.2,214.63 v203.2,276.23 | v193.04,167 191.77,165.74 v191.77,54.61 | v191.77,434.98 192.41,434.34 192.41,295.27 193.04,294.64 193.04,293.37 191.13,291.46 191.13,281.31 v193.04,279.4
  Bottom 0.254: 191.77,434.34 196.22,434.34 IC42.1 | v154.94,434.34 191.77,434.34 | v201.93,172.09 196.85,167 v193.04,167 | v191.77,54.61 192.41,53.98 196.22,53.98 IC35.1 | 191.77,434.34 v191.77,434.98 | v193.04,279.4 196.22,276.23 v203.2,276.23
IM_05\  (via drill 0.61)
  Top 0.254: v147.96,66.04 148.59,66.67 148.59,89.53 v135.25,102.87 | IC42.5 204.47,440.69 203.2,439.42 203.2,407.67 207.01,403.86 207.01,64.77 204.47,62.23 IC35.5
  Bottom 0.254: v147.96,66.04 199.39,66.04 203.84,61.59 IC35.5 | v135.25,102.87 26.04,102.87 20.95,97.79 1.91,97.79 1.27,98.42 1.27,100.97 0,100.97 SV3.BB 0,102.23 1.27,102.23 1.27,120.02 0,121.28 SV8.BB
IM_05\_  (via drill 0.61)
  Top 0.254: v196.22,469.9 199.39,466.73 199.39,443.23 IC42.7 | IC35.7 200.03,60.33 201.29,60.33 IC35.6 | v194.31,64.77 194.31,201.93 | 194.31,201.93 194.31,207.01 194.94,207.65 194.94,211.46 195.58,212.09 IC38.13 | v188.59,440.06 189.87,438.79 189.87,349.88 190.5,349.25 190.5,251.46 193.68,248.28 193.68,216.53 191.77,214.63 191.77,204.47 194.31,201.93
  Bottom 0.254: IC42.6 201.29,441.32 200.03,441.32 IC42.7 198.75,441.32 197.49,440.06 v188.59,440.06 | v196.22,469.9 162.56,469.9 160.66,471.81 IC31.4 | v194.31,64.77 196.22,62.87 197.49,62.87 198.75,61.59 IC35.7
IM_06\  (via drill 0.61)
  Top 0.254: IC36.3 201.93,92.71 200.66,93.98 v200.66,102.87 200.03,103.5 200.03,121.28 200.66,121.92 200.66,130.81 201.29,131.44 201.29,132.08 v201.93,132.72 | v208.91,464.19 210.82,462.28 210.82,381 209.55,379.73 209.55,294.64 212.09,292.1 212.09,221.62 214,219.71 214,205.74 212.72,204.47 212.72,179.07 210.82,177.16 210.82,133.35 v211.46,132.72
  Bottom 0.254: v200.66,102.87 198.75,104.78 25.4,104.78 20.95,100.33 6.99,100.33 5.71,101.6 SV3.FF 5.08,102.23 6.35,102.23 6.35,120.02 5.08,121.28 SV8.FF | v208.91,464.19 201.93,471.17 IC43.3 | v201.93,132.72 v211.46,132.72
IM_06\_  (via drill 0.61)
  Top 0.254: IC43.1 197.49,471.81 198.75,471.81 IC43.2 | v161.29,469.9 161.29,477.52 162.56,478.79 IC31.10 | 198.12,90.81 198.75,90.81 IC36.2 | 198.12,90.81 197.49,90.81 IC36.1 | v199.39,277.5 199.39,162.56 197.49,160.66 197.49,139.06 198.12,138.43 198.12,90.81 | v193.04,466.73 193.04,391.8 194.31,390.52 194.31,295.91 194.94,295.27 194.94,294 191.77,290.83 191.77,284.48 193.04,283.21 IC39.1
  Bottom 0.254: v161.29,469.9 162.56,468.63 193.04,468.63 | 193.04,468.63 196.85,468.63 199.39,471.17 IC43.2 | v199.39,277.5 197.49,277.5 193.68,281.31 IC39.1 | v193.04,466.73 193.04,468.63
IM_07\  (via drill 0.61)
  Top 0.254: v203.2,123.83 203.2,101.6 204.47,100.33 IC36.5 | v207.01,476.88 211.46,472.44 211.46,380.37 210.19,379.1 210.19,295.27 212.72,292.74 212.72,222.25 214.63,220.34 214.63,205.1 213.36,203.84 213.36,178.44 211.46,176.53 211.46,133.99 212.72,132.72 212.72,129.54 v208.91,125.73
  Bottom 0.254: v207.01,476.88 206.38,476.88 204.47,478.79 IC43.5 | v208.91,125.73 207.01,123.83 v203.2,123.83 12.7,123.83 10.79,121.92 SV8.LL 10.16,121.28 11.43,121.28 11.43,118.75 10.79,118.11 10.16,118.11 10.16,102.23 SV3.LL
IM_07\_  (via drill 0.61)
  Top 0.254: 201.93,284.48 200.66,283.21 IC39.4 | v201.93,325.75 201.93,284.48 | v217.81,339.73 v217.81,476.88 | v184.78,100.97 178.44,107.31 178.44,244.47 v179.71,245.75 | v201.29,247.65 201.93,248.28 201.93,284.48
  Bottom 0.254: IC36.6 201.29,98.42 200.03,98.42 IC36.7 198.75,99.69 197.49,100.97 v184.78,100.97 | v201.93,325.75 215.9,339.73 v217.81,339.73 | v217.81,476.88 212.72,481.96 203.84,481.96 202.56,480.69 IC43.6 201.29,479.43 200.03,478.15 | 200.03,478.15 198.75,476.88 158.12,476.88 155.57,479.43 IC31.13 | 200.03,478.15 199.39,478.79 IC43.7 | v179.71,245.75 181.61,247.65 v201.29,247.65
IM_08\  (via drill 0.61)
  Top 0.254: v201.29,121.28 201.29,127.64 201.93,128.27 IC37.3 | v220.34,490.22 223.52,487.05 v223.52,290.83 | v224.16,286.38 v224.16,266.06 | v227.33,266.06 229.24,264.16 v229.24,125.09 | SV3.RR 15.24,102.23 16.51,103.5 16.51,120.02 15.24,121.28 SV8.RR
  Bottom 0.254: SV8.RR 15.88,121.92 17.14,120.65 40.64,120.65 41.91,121.92 200.66,121.92 v201.29,121.28 225.43,121.28 v229.24,125.09 | v220.34,490.22 201.93,508.63 201.93,509.27 IC44.3 | v223.52,290.83 223.52,286.38 v224.16,286.38 | v224.16,266.06 v227.33,266.06
IM_08\_  (via drill 0.61)
  Top 0.254: v214.63,287.65 215.26,288.29 v215.26,494.03 | IC44.1 197.49,509.9 198.75,509.9 IC44.2 | v154.94,513.72 154.94,544.83 152.4,547.37 IC32.1 | v200.66,176.53 200.66,132.08 199.39,130.81 IC37.2 | v188.59,182.25 188.59,241.94 189.23,242.57 189.23,287.02 v188.59,287.65
  Bottom 0.254: IC37.1 197.49,128.91 198.75,128.91 IC37.2 | 205.1,287.65 203.84,288.93 IC39.10 | 205.1,287.65 v214.63,287.65 | v215.26,494.03 200.03,509.27 199.39,509.27 IC44.2 | v154.94,513.72 157.48,511.18 196.22,511.18 IC44.1 | v200.66,176.53 194.94,182.25 v188.59,182.25 | v188.59,287.65 192.41,291.46 193.68,291.46 194.31,290.83 194.31,287.65 205.1,287.65
IM_09\  (via drill 0.61)
  Top 0.254: v203.2,125.09 203.2,134.62 204.47,135.89 IC37.5
  Bottom 0.254: v203.2,125.09 202.56,124.46 -20.95,124.46 -22.86,122.56 SV8.F -23.5,121.92 -24.13,121.92 -24.13,118.75 -23.5,118.11 -22.86,118.11 -22.86,102.23 SV3.F
IM_09\_  (via drill 0.61)
  Top 0.254: v158.75,379.73 158.75,546.1 160.02,547.37 IC32.4 | v156.21,377.19 152.4,373.38 152.4,162.56 v153.03,161.93 | v198.75,160.66 199.39,160.02 199.39,138.43 IC37.7
  Bottom 0.254: IC37.7 200.03,136.53 201.29,136.53 IC37.6 | v156.21,377.19 v158.75,379.73 | v153.03,161.93 154.31,160.66 v198.75,160.66
IM_10\
  Top 0.254: SV3.L -17.78,102.23 -19.05,103.5 -19.05,120.02 -17.78,121.28 SV8.L
IM_11\  (via drill 0.61)
  Top 0.254: v207.01,517.52 206.38,516.89 206.38,477.52 205.74,476.88 205.74,444.5 208.28,441.96 208.28,394.97 209.55,393.7 209.55,382.27 208.28,381 208.28,293.37 210.19,291.46 210.19,179.07 208.91,177.8 v208.91,127 | v-8.26,125.73 -12.06,121.92 SV8.R
  Bottom 0.254: v207.01,517.52 205.1,517.52 IC44.5 | v208.91,127 208.28,126.36 194.31,126.36 193.04,125.09 -7.62,125.09 v-8.26,125.73 | SV3.R -12.7,102.23 -12.7,118.11 -13.34,118.11 -13.97,118.75 -13.97,121.92 -13.34,121.92 SV8.R
IM_11\_  (via drill 0.61)
  Top 0.254: v191.77,294.64 191.13,295.27 191.13,434.34 190.5,434.98 190.5,514.35 196.22,520.07 199.39,520.07 199.39,519.43 IC44.7
  Bottom 0.254: v191.77,294.64 195.58,290.83 IC39.13 | IC44.6 201.29,517.52 200.03,517.52 IC44.7
INT_RQ\  (via drill 0.61)
  Top 0.254: v185.42,17.78 189.23,21.59 189.23,140.34 187.96,141.6 187.96,181.61 186.69,182.88 186.69,311.79 187.96,313.06 187.96,382.9 186.69,384.18 v186.69,530.86 | v193.68,537.85 203.2,547.37 IC45.5
  Bottom 0.254: v185.42,17.78 87.63,17.78 85.72,15.88 IC16.6 | v186.69,530.86 v193.68,537.85
IOP_1  (via drill 0.61)
  Top 0.254: v-7.62,36.2 -7.62,23.5 SV1.V | IC87.5 402.59,245.11 403.86,246.38 403.86,382.27 402.59,383.54 IC88.10 | v115.57,52.07 v97.16,33.66 | v413.38,52.07 414.65,53.34 v414.65,235.59
  Bottom 0.254: SV6.V -8.26,40.64 -8.89,40.64 -8.89,37.47 v-7.62,36.2 -5.08,33.66 v97.16,33.66 | v115.57,52.07 116.2,51.44 208.91,51.44 210.19,52.7 406.4,52.7 407.04,52.07 v413.38,52.07 | v414.65,235.59 408.31,241.94 404.5,241.94 403.23,243.21 IC87.5
IOP_2  (via drill 0.61)
  Top 0.254: SV1.Z -3.17,22.86 -4.45,21.59 -21.59,21.59 -21.59,34.92 -24.13,37.47 -24.13,38.73 -23.5,39.37 -3.17,39.37 -3.17,40.64 SV6.Z -1.91,40.64 v3.17,45.72 | v402.59,371.48 402.59,252.73 IC87.10 | v266.7,42.55 270.51,46.35 v270.51,147.32 | v372.11,153.67 375.29,156.84 v375.29,249.56
  Bottom 0.254: v402.59,371.48 410.21,371.48 410.21,381 408.94,382.27 397.51,382.27 395.61,384.18 IC88.13 | v3.17,45.72 73.03,45.72 74.93,43.81 205.1,43.81 206.38,42.55 v266.7,42.55 | v270.51,147.32 276.86,153.67 v372.11,153.67 | v375.29,249.56 379.1,253.37 400.69,253.37 401.95,252.09 IC87.10
IOP_4  (via drill 0.61)
  Top 0.254: v2.54,36.2 2.54,23.5 SV1.DD | v390.52,422.27 390.52,364.49 387.99,361.95 387.99,335.28 388.62,334.64 388.62,250.19 v389.25,249.56 389.25,163.19 v390.52,161.93 | v393.06,424.81 394.33,426.08 394.33,471.81 IC90.2 | v27.94,77.47 27.94,54.61 17.14,54.61 3.17,40.64 SV6.DD | v295.27,81.92 300.99,87.63 v300.99,160.02
  Bottom 0.254: v2.54,36.2 3.81,37.47 3.81,40.01 2.54,40.01 SV6.DD | v389.25,249.56 393.06,249.56 394.33,250.82 IC87.13 | v390.52,422.27 v393.06,424.81 | v27.94,77.47 33.02,82.55 96.52,82.55 97.16,81.92 v295.27,81.92 | v300.99,160.02 301.62,159.38 387.99,159.38 v390.52,161.93
LDMF  (via drill 0.61)
  Top 0.254: v409.57,398.78 409.57,493.39 407.04,493.39 405.76,492.12 IC91.6 | v551.18,157.48 552.45,158.75 552.45,236.22 550.54,238.12 v550.54,389.89 | IC136.3 598.17,378.46 600.71,381 600.71,383.54 IC136.11
  Bottom 0.254: v409.57,398.78 418.46,389.89 v550.54,389.89 595.63,389.89 600.08,385.44 IC136.11 | v551.18,157.48 550.54,158.12 522.61,158.12 521.34,156.84 IC115.11
LDMF\  (via drill 0.61)
  Top 0.254: v275.59,173.99 275.59,182.88 273.05,185.42 IC61.1 | v426.08,180.97 428.62,183.51 428.62,242.57 427.99,243.21 427.99,290.19 423.55,294.64 423.55,362.58 424.18,363.22 424.18,375.29 422.27,377.19 422.27,455.93 423.55,457.2 423.55,469.9 v422.27,471.17 | IC91.5 402.59,490.22 398.78,486.41 398.78,474.98 397.51,473.71 IC90.3
  Bottom 0.254: v275.59,173.99 277.5,172.09 316.87,172.09 317.5,171.45 332.74,171.45 333.38,172.09 417.19,172.09 v426.08,180.97 | v422.27,471.17 419.1,474.35 399.42,474.35 398.14,473.07 IC90.3
LPB_00  (via drill 0.61)
  Top 0.254: v444.5,341 444.5,332.74 443.23,331.47 IC96.5 | v134.62,349.25 126.36,357.5 126.36,360.68 M916_9.T2 | v585.47,55.88 584.84,56.52 v584.84,337.19
  Bottom 0.254: v134.62,349.25 171.45,349.25 173.35,351.15 226.06,351.15 227.33,349.88 435.61,349.88 v444.5,341 581.02,341 v584.84,337.19 | v585.47,55.88 598.17,43.18 IC126.12
LPB_00\  (via drill 0.61)
  Top 0.254: v588.01,50.8 v588.01,313.69
  Bottom 0.254: v588.01,50.8 595.63,43.18 IC126.13 | v588.01,313.69 593.09,318.77 IC135.1
LPB_01  (via drill 0.61)
  Top 0.254: v264.16,407.04 263.52,406.4 v263.52,371.48 | v549.91,113.03 542.92,120.02 542.92,182.25 539.12,186.06 v539.12,410.21
  Bottom 0.254: 447.04,410.21 447.04,415.29 446.4,415.93 445.13,415.93 443.87,414.65 IC98.10 | 447.04,410.21 357.5,410.21 354.33,407.04 v264.16,407.04 | v263.52,371.48 262.89,370.84 137.79,370.84 131.44,364.49 129.54,364.49 M916_9.U2 | v549.91,113.03 593.09,69.85 607.06,69.85 607.06,73.66 606.42,74.3 603.88,74.3 598.8,79.38 IC127.12 | 447.04,410.21 v539.12,410.21
LPB_01\
  Top 0.254: IC127.13 595.63,81.28 596.9,82.55 596.9,229.87 594.36,232.41 594.36,259.08 596.9,261.62 596.9,317.5 595.63,318.77 IC135.2
LPB_02  (via drill 0.61)
  Top 0.254: v443.23,371.48 443.23,369.57 IC97.5 | v137.79,389.89 133.35,385.44 133.35,361.95 132.72,361.31 M916_9.V2 | v566.42,139.06 563.25,142.24 563.25,166.37 565.15,168.28 v565.15,362.58
  Bottom 0.254: v443.23,371.48 441.32,373.38 422.91,373.38 407.04,389.25 276.86,389.25 275.59,387.99 149.22,387.99 147.32,389.89 v137.79,389.89 | v566.42,139.06 577.22,139.06 597.53,118.75 IC128.12 | v565.15,362.58 561.34,366.39 457.2,366.39 455.93,365.12 446.4,365.12 443.87,367.67 IC97.5
LPB_02\  (via drill 0.61)
  Top 0.254: v589.28,311.79 589.28,125.73 595.63,119.38 IC128.13
  Bottom 0.254: v589.28,311.79 595.63,318.13 596.26,318.13 597.53,319.4 IC135.3
LPB_03  (via drill 0.61)
  Top 0.254: v583.57,335.92 584.2,335.28 584.2,40.64 593.09,31.75 604.52,31.75 604.52,36.2 605.79,37.47 605.79,40.64 IC126.9 | v40.01,458.47 40.01,434.98 39.37,434.34 M916_10.A2 | v347.98,462.28 349.25,461.01 349.25,452.75 348.62,452.12 v348.62,346.71 | v441.32,341 443.23,339.09 IC96.10
  Bottom 0.254: v583.57,335.92 445.13,335.92 443.87,337.19 IC96.10 | v40.01,458.47 43.18,461.64 347.35,461.64 v347.98,462.28 | v348.62,346.71 354.33,341 v441.32,341
LPB_03\  (via drill 0.61)
  Top 0.254: v610.24,309.25 610.24,263.52 613.41,260.35 613.41,32.38 607.7,32.38 607.06,33.02 607.06,39.37 608.33,40.64 IC126.8
  Bottom 0.254: v610.24,309.25 600.71,318.77 IC135.4
LPB_04  (via drill 0.61)
  Top 0.254: v361.95,392.43 v363.22,391.16 | v45.09,405.76 43.18,407.67 43.18,425.45 42.55,426.08 42.55,430.53 M916_10.B2 | v563.88,117.47 559.43,121.92 v559.43,342.26 | v431.8,378.46 v431.8,352.43
  Bottom 0.254: 436.25,382.9 431.8,387.35 410.21,387.35 406.4,391.16 v363.22,391.16 | 436.25,382.9 442.6,376.56 IC97.10 | v361.95,392.43 356.87,397.51 297.18,397.51 294,400.69 235.59,400.69 233.68,402.59 233.68,407.04 140.97,407.04 140.34,407.67 101.6,407.67 99.69,405.76 v45.09,405.76 | v563.88,117.47 596.9,84.45 599.44,84.45 600.08,85.09 612.14,85.09 612.14,83.82 610.87,82.55 608.33,82.55 606.42,80.64 IC127.9 | v559.43,342.26 549.27,352.43 v431.8,352.43 | 436.25,382.9 v431.8,378.46
LPB_04\
  Bottom 0.254: IC135.5 603.88,319.4 605.79,317.5 614.04,317.5 614.04,81.28 608.33,81.28 IC127.8
LPB_05  (via drill 0.61)
  Top 0.254: v455.3,405.76 454.66,405.13 454.66,339.73 458.47,335.92 v458.47,143.51 | v46.99,448.94 46.99,435.61 45.72,434.34 M916_10.C2 | v371.48,447.68 377.19,441.96 v377.19,408.31
  Bottom 0.254: v455.3,405.76 452.75,408.31 445.13,408.31 443.87,407.04 IC98.5 442.6,405.76 441.32,404.5 432.44,404.5 431.17,405.76 379.73,405.76 v377.19,408.31 | v458.47,143.51 600.08,143.51 605.79,137.79 605.79,119.38 IC128.9 | v46.99,448.94 48.9,450.85 304.17,450.85 307.34,447.68 v371.48,447.68
LPB_05\
  Bottom 0.254: IC135.12 598.8,327.02 600.08,327.02 IC135.11 600.71,326.39 601.98,325.12 | 601.98,325.12 605.79,321.31 IC135.6 | 601.98,325.12 601.98,318.77 603.88,316.87 613.41,316.87 613.41,161.29 608.97,156.84 608.33,156.84 608.33,119.38 IC128.8
LPB_NOT_EQ_1  (via drill 0.61)
  Top 0.254: v43.18,190.5 43.18,187.96 IC12.5 | v223.52,192.41 224.16,193.04 v224.16,231.14 | v379.1,234.31 381.63,236.85 v381.63,259.08 | v611.5,263.52 611.5,323.21 608.33,326.39 IC135.8
  Bottom 0.254: v43.18,190.5 43.81,189.87 146.05,189.87 148.59,192.41 v223.52,192.41 | v224.16,231.14 229.87,236.85 242.57,236.85 244.47,234.95 317.5,234.95 318.13,234.31 v379.1,234.31 | v381.63,259.08 382.27,258.44 606.42,258.44 v611.5,263.52
LPB_TO_DTB  (via drill 0.61)
  Top 0.254: IC96.4 441.32,329.56 442.6,328.3 444.5,328.3 444.5,331.47 445.77,332.74 445.77,336.55 IC96.9 445.77,339.09 445.77,361.95 440.69,367.03 IC97.4 440.69,369.57 441.96,370.84 441.96,372.11 445.13,375.29 IC97.9 445.77,377.19 440.69,382.27 440.69,405.13 IC98.4 440.69,407.67 445.77,412.75 IC98.9 | v48.26,410.21 43.81,414.65 43.81,426.08 43.18,426.72 43.18,477.52 44.45,478.79 IC15.10
  Bottom 0.254: v48.26,410.21 48.9,409.57 234.31,409.57 234.95,408.94 354.96,408.94 356.87,410.85 442.6,410.85 445.13,413.38 IC98.9
M-STOP\  (via drill 0.61)
  Top 0.254: v346.07,246.38 349.88,250.19 v349.88,262.89 | v445.77,269.88 445.77,280.67 IC95.6 | v32.38,466.73 25.4,459.74 25.4,240.66 v24.77,240.03 | v318.13,237.49 318.13,240.66 320.04,242.57 IC76.4
  Bottom 0.254: v346.07,246.38 322.58,246.38 320.68,244.47 IC76.4 | v349.88,262.89 356.87,269.88 v445.77,269.88 | v32.38,466.73 36.2,466.73 41.27,471.81 IC15.4 | M916_20.L1 -13.34,240.03 -12.06,238.76 23.5,238.76 v24.77,240.03 29.21,235.59 82.55,235.59 84.45,237.49 225.43,237.49 226.06,238.12 317.5,238.12 v318.13,237.49
MB_TO_DTB\
  Top 0.254: IC139.1 593.73,490.86 595,490.86 IC139.2 | IC139.4 601.35,490.86 602.62,490.86 IC139.5
  Bottom 0.254: 603.88,493.39 603.25,492.76 IC139.5 | 603.88,493.39 608.33,497.84 IC139.8 | 603.88,493.39 597.53,493.39 596.26,492.12 IC139.2
MC00  (via drill 0.61)
  Top 0.254: v495.3,283.85 495.94,283.21 495.94,193.68 496.57,193.04 v496.57,126.36 | v424.81,443.87 427.99,440.69 427.99,342.26 431.17,339.09 v431.17,295.91
  Bottom 0.254: IC73.12 316.87,118.75 316.23,118.75 316.23,110.49 316.87,109.86 320.68,109.86 321.94,111.12 IC73.5 323.21,112.39 324.49,113.67 325.12,113.67 334.01,122.56 492.76,122.56 v496.57,126.36 | IC133.5 602.62,282.57 600.71,284.48 525.14,284.48 524.51,283.85 v495.3,283.85 487.05,292.1 434.98,292.1 v431.17,295.91 | v424.81,443.87 87,443.87 83.82,440.69 M916_10.S1
MC00\  (via drill 0.61)
  Top 0.254: v215.9,188.59 217.17,187.32 v217.17,141.6 | v297.81,132.08 298.45,131.44 v298.45,118.75 | v290.83,513.08 290.19,513.72 290.19,522.61 290.83,523.24 290.83,558.16 287.65,558.16 286.38,556.89 IC69.9 | v255.91,490.22 252.09,486.41 252.09,313.06 252.73,312.42 252.73,273.69 254,272.42 254,203.84 252.73,202.56 v252.73,139.06
  Bottom 0.254: v215.9,188.59 147.32,188.59 146.69,189.23 40.64,189.23 36.2,193.68 IC12.13 | v217.17,141.6 222.88,135.89 245.75,135.89 249.56,132.08 252.73,132.08 | 252.73,132.08 v297.81,132.08 | v298.45,118.75 307.98,109.22 322.58,109.22 324.49,111.12 IC73.6 | v290.83,513.08 267.97,490.22 v255.91,490.22 | v252.73,139.06 252.73,132.08
MC01  (via drill 0.61)
  Top 0.254: v324.49,165.1 325.75,163.83 325.75,121.28 325.12,120.65 IC73.9 | v85.72,485.77 v85.72,462.92 85.72,437.51 M916_10.T1 | v391.8,468 393.7,469.9 393.7,477.52 394.97,478.79 IC90.13 | v299.72,169.54 299.72,254 303.53,257.81 303.53,398.14 307.98,402.59 v307.98,480.69
  Bottom 0.254: v324.49,165.1 323.85,165.74 316.87,165.74 315.6,167 IC74.2 314.32,168.28 313.06,169.54 v299.72,169.54 | v85.72,485.77 67.94,503.56 47.62,503.56 42.55,508.63 IC6.11 | v391.8,468 389.25,465.45 333.38,465.45 330.2,462.28 86.36,462.28 v85.72,462.92 | v307.98,480.69 309.25,481.96 393.06,481.96 394.33,480.69 IC90.13
MC01\  (via drill 0.61)
  Top 0.254: v331.47,121.28 332.11,121.92 332.11,190.5 328.93,193.68 328.93,252.73 328.3,253.37 328.3,264.8 328.93,265.43 v328.93,300.36 v328.93,464.82
  Bottom 0.254: v331.47,121.28 329.56,121.28 328.3,120.02 IC73.8 | IC68.3 280.04,469.26 282.57,466.73 327.02,466.73 v328.93,464.82 334.64,470.54 355.6,470.54 363.22,478.15 400.69,478.15 401.95,479.43 IC90.10 | v328.93,300.36 335.92,300.36 339.73,304.17 368.94,304.17 369.57,303.53 604.52,303.53 604.52,299.72 605.15,299.08 609.6,299.08 609.6,287.02 605.79,283.21 IC133.6
MC02  (via drill 0.61)
  Top 0.254: IC140.1 593.73,528.96 595,528.96 IC140.2 | v110.49,551.82 90.17,531.5 90.17,440.69 M916_10.U1 | v298.45,170.81 299.08,171.45 299.08,254.63 302.26,257.81 v302.26,271.14 | v292.74,274.95 292.1,275.59 292.1,294 291.46,294.64 291.46,337.82 292.74,339.09 292.74,467.36 292.1,468 292.1,495.94 292.74,496.57 292.74,509.9 289.56,513.08 289.56,546.1 290.19,546.74 290.19,553.09 v289.56,553.72 | v284.48,546.74 284.48,552.45 283.21,553.72 283.21,554.99 IC69.10
  Bottom 0.254: 281.31,554.36 278.76,551.82 v110.49,551.82 | 281.31,554.36 282.57,555.62 IC69.10 | v298.45,170.81 319.4,170.81 321.94,168.28 IC74.5 | v302.26,271.14 298.45,274.95 v292.74,274.95 | v289.56,553.72 288.93,554.36 281.31,554.36 | v284.48,546.74 551.82,546.74 570.87,527.68 591.18,527.68 592.46,528.96 IC140.1
MC02\  (via drill 0.61)
  Top 0.254: v326.39,117.47 326.39,165.1 325.12,166.37 IC74.6 | v532.76,285.75 532.76,177.16 533.4,176.53 v533.4,165.74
